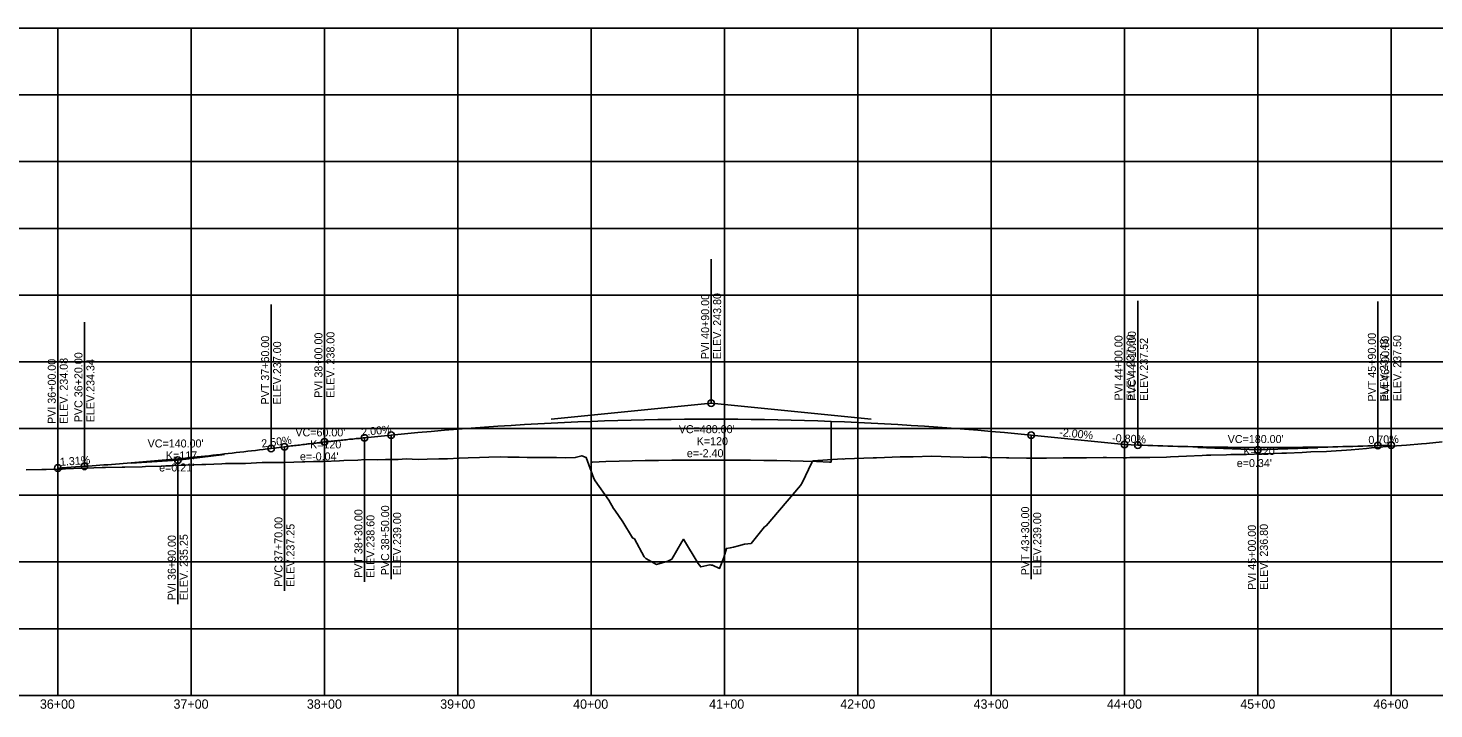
# Model space of a CAD drawing. Extents: x 976639 to 985448, y 1524031 to 1526806.
# Drawn here: x 983504 to 984558, y 1524031 to 1524541 of the extents above; entities that cross this region are included whole.
import ezdxf

# ---------------------------------------------------------------- set-up
doc = ezdxf.new("R2010")
doc.units = 0
for name, color, linetype in [('B_Concrete', 7, 'Continuous'), ('Default', 7, 'Continuous'), ('R_Axis', 7, 'Continuous'), ('R_Axis Annot', 7, 'Continuous'), ('R_Grid', 7, 'Continuous'), ('R_Vert Alg', 7, 'Continuous'), ('R_Vert Alg Annot', 7, 'Continuous'), ('S_WORKING_LINES', 7, 'Continuous')]:
    doc.layers.add(name, color=color, linetype=linetype)

msp = doc.modelspace()

# ---------------------------------------------------------------- linework, layer by layer
at = {"layer": 'B_Concrete'}
for p, q in [((983926.2, 1524246.7), (983926.2, 1524216.2)), ((984106.2, 1524246.7), (984106.2, 1524216.2))]:
    msp.add_line(p, q, dxfattribs=at)
msp.add_lwpolyline([(983926.2, 1524216.2), (983927.3, 1524216.2), (983937.2, 1524216.6), (983947.1, 1524216.9), (983956.9, 1524217.1), (983966.8, 1524217.4), (983976.7, 1524217.5), (983986.6, 1524217.7), (983996.4, 1524217.8), (984006.3, 1524217.8), (984026.1, 1524217.8), (984035.9, 1524217.8), (984045.8, 1524217.7), (984055.7, 1524217.5), (984065.5, 1524217.4), (984075.4, 1524217.1), (984085.3, 1524216.9), (984095.2, 1524216.6), (984105, 1524216.2), (984106.2, 1524216.2)], dxfattribs=at)
at = {"layer": 'Default'}
msp.add_lwpolyline([(983502.5, 1524210.5), (983514.2, 1524210.8), (983517.4, 1524210.8), (983529.4, 1524211), (983532, 1524211.1), (983544.3, 1524211.7), (983547.1, 1524211.8), (983559.4, 1524212.2), (983561.9, 1524212.3), (983574.6, 1524212.4), (983576.6, 1524212.5), (983589.4, 1524212.8), (983591.9, 1524212.9), (983604.3, 1524213.3), (983607.2, 1524213.4), (983619.2, 1524214), (983622.3, 1524214), (983634.3, 1524214.5), (983637.2, 1524214.5), (983649.3, 1524215), (983652.1, 1524215.1), (983664.4, 1524215.1), (983666.9, 1524215.2), (983679.5, 1524215.9), (983681.8, 1524216), (983694.5, 1524216), (983696.8, 1524216), (983709.7, 1524216.4), (983711.4, 1524216.5), (983718.1, 1524216.7), (983724.2, 1524216.8), (983725.3, 1524216.8), (983737.5, 1524217.2), (983740.8, 1524217.4), (983751.2, 1524217.8), (983756.5, 1524218.1), (983766.1, 1524217.9), (983772.1, 1524218.2), (983781.6, 1524218.3), (983787.4, 1524218.6), (983796.5, 1524218.3), (983803.2, 1524218.5), (983811.9, 1524218.6), (983818.5, 1524218.8), (983827.2, 1524219.2), (983834, 1524219.5), (983842.6, 1524219.7), (983849.4, 1524219.9), (983857.9, 1524220.1), (983863.8, 1524219.9), (983872.1, 1524220), (983878.2, 1524219.8), (983886.3, 1524219.8), (983892.6, 1524219.6), (983900.3, 1524219.7), (983906.9, 1524219.5), (983914.3, 1524219.6), (983919.1, 1524221), (983922.5, 1524219.6), (983928.3, 1524204), (983929.2, 1524202.2), (983939.4, 1524187.7), (983943, 1524181.4), (983944, 1524180.2), (983949.9, 1524171.4), (983957.2, 1524159.4), (983958.7, 1524158.7), (983966, 1524145.2), (983966.9, 1524144.3), (983967.3, 1524143.9), (983975.3, 1524139.6), (983983.6, 1524141.9), (983986.7, 1524143.4), (983994.1, 1524156.5), (983995.5, 1524158.4), (984006.4, 1524140.3), (984008.4, 1524137.7), (984015.3, 1524139.3), (984016.2, 1524139.1), (984017.1, 1524139.1), (984022.5, 1524136.5), (984025.7, 1524144.8), (984027.7, 1524151.5), (984030.5, 1524151.9), (984032.9, 1524152.6), (984036.8, 1524153.6), (984041.2, 1524154.8), (984046.1, 1524155.3), (984055.3, 1524166.5), (984056.3, 1524167.7), (984057.4, 1524168.4), (984083.2, 1524198.6), (984084.4, 1524200.8), (984091.8, 1524216), (984092.4, 1524216.7), (984092.7, 1524217.2), (984103.5, 1524218), (984114.8, 1524218.6), (984115.8, 1524218.5), (984116.8, 1524218.6), (984137.6, 1524219.5), (984140.2, 1524219.5), (984158, 1524220.3), (984161.9, 1524220.2), (984167.7, 1524220.1), (984181.4, 1524220.6), (984188.7, 1524220.5), (984195.5, 1524220.1), (984205.1, 1524219.9), (984209.3, 1524219.7), (984218.7, 1524219.9), (984222.7, 1524219.9), (984224, 1524219.8), (984237.7, 1524219.4), (984239.4, 1524219.4), (984252.7, 1524219.3), (984254.7, 1524219.3), (984267.7, 1524219.3), (984280.3, 1524219.4), (984282.7, 1524219.4), (984285.1, 1524219.5), (984297.7, 1524219.4), (984310.3, 1524219.6), (984312.7, 1524219.6), (984312.7, 1524219.6), (984325.3, 1524219.5), (984327.7, 1524219.5), (984330.1, 1524219.6), (984342.7, 1524219.7), (984345.3, 1524219.8), (984357.7, 1524220), (984360.7, 1524220.1), (984372.7, 1524220.6), (984384.5, 1524221.2), (984387.7, 1524221.3), (984390.9, 1524221.4), (984402.7, 1524221.7), (984406, 1524221.8), (984417.7, 1524221.9), (984429.2, 1524222.3), (984432.7, 1524222.5), (984444.3, 1524222.8), (984447.7, 1524223), (984459.5, 1524223.5), (984462.7, 1524223.6), (984465.9, 1524223.8), (984477.7, 1524224.2), (984481.1, 1524224.5), (984492.7, 1524225.2), (984496.2, 1524225.5), (984507.7, 1524226.5), (984511.3, 1524226.8), (984522.7, 1524227.8), (984526.3, 1524228.1), (984537.7, 1524229), (984549, 1524229.8), (984552.7, 1524230.1), (984564.3, 1524231.3)], dxfattribs=at)
at = {"layer": 'R_Axis'}
msp.add_line((982626.2, 1524041.4), (985426.2, 1524041.4), dxfattribs=at)
at = {"layer": 'R_Grid'}
for p, q in [((982626.2, 1524541.4), (985426.2, 1524541.4)), ((982626.2, 1524541.4), (985426.2, 1524541.4)), ((983526.2, 1524041.4), (983526.2, 1524541.4)), ((983626.2, 1524041.4), (983626.2, 1524541.4)), ((983726.2, 1524041.4), (983726.2, 1524541.4)), ((983826.2, 1524041.4), (983826.2, 1524541.4)), ((983926.2, 1524041.4), (983926.2, 1524541.4)), ((984026.2, 1524041.4), (984026.2, 1524541.4)), ((984126.2, 1524041.4), (984126.2, 1524541.4)), ((984226.2, 1524041.4), (984226.2, 1524541.4)), ((984326.2, 1524041.4), (984326.2, 1524541.4)), ((984426.2, 1524041.4), (984426.2, 1524541.4)), ((984526.2, 1524041.4), (984526.2, 1524541.4)), ((982626.2, 1524491.4), (985426.2, 1524491.4)), ((982626.2, 1524441.4), (985426.2, 1524441.4)), ((982626.2, 1524391.4), (985426.2, 1524391.4)), ((982626.2, 1524341.4), (985426.2, 1524341.4)), ((982626.2, 1524291.4), (985426.2, 1524291.4)), ((982626.2, 1524241.4), (985426.2, 1524241.4)), ((982626.2, 1524191.4), (985426.2, 1524191.4)), ((982626.2, 1524141.4), (985426.2, 1524141.4)), ((982626.2, 1524091.4), (985426.2, 1524091.4))]:
    msp.add_line(p, q, dxfattribs=at)
at = {"layer": 'R_Vert Alg'}
for p, q in [((983896.2, 1524248.4), (984016.2, 1524260.4)), ((984016.2, 1524260.4), (984136.2, 1524248.4)), ((983711.2, 1524229.5), (983726.2, 1524231.4)), ((983726.2, 1524231.4), (983741.2, 1524232.9)), ((983756.2, 1524234.4), (983776.2, 1524236.4)), ((984256.2, 1524236.4), (984326.2, 1524229.4)), ((983616.2, 1524217.7), (983651.2, 1524222)), ((983686.2, 1524226.4), (983696.2, 1524227.7)), ((984326.2, 1524229.4), (984336.2, 1524229)), ((984381.2, 1524227.2), (984426.2, 1524225.4)), ((984426.2, 1524225.4), (984471.2, 1524227)), ((984516.2, 1524228.6), (984526.2, 1524228.9)), ((983526.2, 1524211.8), (983546.2, 1524213.1)), ((983581.2, 1524215.4), (983616.2, 1524217.7))]:
    msp.add_line(p, q, dxfattribs=at)
for points in [[(983776.2, 1524236.4), (983786.2, 1524237.4), (983796.2, 1524238.3), (983806.2, 1524239.2), (983816.2, 1524240.1), (983826.2, 1524240.9), (983836.2, 1524241.7), (983846.2, 1524242.4), (983856.2, 1524243.1), (983866.2, 1524243.7), (983876.2, 1524244.3), (983886.2, 1524244.9), (983896.2, 1524245.4), (983906.2, 1524245.9), (983916.2, 1524246.3), (983926.2, 1524246.7), (983936.2, 1524247.1), (983946.2, 1524247.4), (983956.2, 1524247.7), (983966.2, 1524247.9), (983976.2, 1524248.1), (983986.2, 1524248.2), (983996.2, 1524248.3), (984006.2, 1524248.4), (984026.2, 1524248.4), (984036.2, 1524248.3), (984046.2, 1524248.2), (984056.2, 1524248.1), (984066.2, 1524247.9), (984076.2, 1524247.7), (984086.2, 1524247.4), (984096.2, 1524247.1), (984106.2, 1524246.7), (984116.2, 1524246.3), (984126.2, 1524245.9), (984136.2, 1524245.4), (984146.2, 1524244.9), (984156.2, 1524244.3), (984166.2, 1524243.7), (984176.2, 1524243.1), (984186.2, 1524242.4), (984196.2, 1524241.7), (984206.2, 1524240.9), (984216.2, 1524240.1), (984226.2, 1524239.2), (984236.2, 1524238.3), (984246.2, 1524237.4), (984256.2, 1524236.4)], [(983696.2, 1524227.7), (983697.4, 1524227.8), (983698.7, 1524228), (983699.9, 1524228.1), (983701.2, 1524228.3), (983702.4, 1524228.4), (983703.7, 1524228.6), (983704.9, 1524228.7), (983706.2, 1524228.9), (983707.4, 1524229), (983708.7, 1524229.2), (983709.9, 1524229.3), (983711.2, 1524229.5), (983712.4, 1524229.6), (983713.7, 1524229.8), (983714.9, 1524229.9), (983716.2, 1524230.1), (983717.4, 1524230.2), (983718.7, 1524230.4), (983719.9, 1524230.5), (983721.2, 1524230.7), (983722.4, 1524230.8), (983723.7, 1524230.9), (983724.9, 1524231.1), (983727.4, 1524231.4), (983728.7, 1524231.5), (983729.9, 1524231.6), (983731.2, 1524231.8), (983732.4, 1524231.9), (983733.7, 1524232.1), (983734.9, 1524232.2), (983736.2, 1524232.3), (983737.4, 1524232.5), (983738.7, 1524232.6), (983739.9, 1524232.7), (983741.2, 1524232.9), (983742.4, 1524233), (983743.7, 1524233.1), (983744.9, 1524233.3), (983746.2, 1524233.4), (983747.4, 1524233.5), (983748.7, 1524233.7), (983749.9, 1524233.8), (983751.2, 1524233.9), (983752.4, 1524234), (983753.7, 1524234.2), (983754.9, 1524234.3), (983756.2, 1524234.4)], [(983546.2, 1524213.1), (983549.1, 1524213.3), (983552, 1524213.5), (983554.9, 1524213.7), (983557.8, 1524213.9), (983560.8, 1524214.1), (983563.7, 1524214.3), (983566.6, 1524214.5), (983569.5, 1524214.7), (983572.4, 1524215), (983575.3, 1524215.2), (983578.3, 1524215.4), (983581.2, 1524215.6), (983584.1, 1524215.9), (983587, 1524216.1), (983589.9, 1524216.4), (983592.8, 1524216.6), (983595.8, 1524216.9), (983598.7, 1524217.1), (983601.6, 1524217.4), (983604.5, 1524217.6), (983607.4, 1524217.9), (983610.3, 1524218.2), (983613.3, 1524218.4), (983619.1, 1524219), (983622, 1524219.3), (983624.9, 1524219.6), (983627.8, 1524219.9), (983630.8, 1524220.1), (983633.7, 1524220.4), (983636.6, 1524220.7), (983639.5, 1524221), (983642.4, 1524221.4), (983645.3, 1524221.7), (983648.3, 1524222), (983651.2, 1524222.3), (983654.1, 1524222.6), (983657, 1524223), (983659.9, 1524223.3), (983662.8, 1524223.6), (983665.8, 1524224), (983668.7, 1524224.3), (983671.6, 1524224.6), (983674.5, 1524225), (983677.4, 1524225.3), (983680.3, 1524225.7), (983683.3, 1524226.1), (983686.2, 1524226.4)], [(984336.2, 1524229), (984339.9, 1524228.9), (984343.7, 1524228.7), (984347.4, 1524228.6), (984351.2, 1524228.5), (984354.9, 1524228.3), (984358.7, 1524228.2), (984362.4, 1524228.1), (984366.2, 1524228), (984369.9, 1524227.9), (984373.7, 1524227.8), (984377.4, 1524227.7), (984381.2, 1524227.6), (984384.9, 1524227.6), (984388.7, 1524227.5), (984392.4, 1524227.4), (984396.2, 1524227.4), (984399.9, 1524227.3), (984403.7, 1524227.3), (984407.4, 1524227.2), (984411.2, 1524227.2), (984414.9, 1524227.2), (984418.7, 1524227.1), (984422.4, 1524227.1), (984429.9, 1524227.1), (984433.7, 1524227.1), (984437.4, 1524227.1), (984441.2, 1524227.1), (984444.9, 1524227.1), (984448.7, 1524227.1), (984452.4, 1524227.2), (984456.2, 1524227.2), (984459.9, 1524227.3), (984463.7, 1524227.3), (984467.4, 1524227.3), (984471.2, 1524227.4), (984474.9, 1524227.5), (984478.7, 1524227.5), (984482.4, 1524227.6), (984486.2, 1524227.7), (984489.9, 1524227.8), (984493.7, 1524227.9), (984497.4, 1524228), (984501.2, 1524228.1), (984504.9, 1524228.2), (984508.7, 1524228.3), (984512.4, 1524228.4), (984516.2, 1524228.6)]]:
    msp.add_lwpolyline(points, dxfattribs=at)
at = {"layer": 'R_Vert Alg Annot'}
for p, q in [((984016.2, 1524290.4), (984016.2, 1524368.4)), ((983726.2, 1524261.4), (983726.2, 1524339.4)), ((984326.2, 1524259.4), (984326.2, 1524337.4)), ((984336.2, 1524259), (984336.2, 1524337)), ((984516.2, 1524258.6), (984516.2, 1524336.6)), ((984526.2, 1524258.9), (984526.2, 1524336.9)), ((983686.2, 1524256.4), (983686.2, 1524334.4)), ((983526.2, 1524241.8), (983526.2, 1524319.8)), ((983546.2, 1524243.1), (983546.2, 1524321.1)), ((984016.2, 1524260.4), (984016.2, 1524290.4)), ((983686.2, 1524226.4), (983686.2, 1524256.4)), ((983726.2, 1524231.4), (983726.2, 1524261.4)), ((984326.2, 1524229.4), (984326.2, 1524259.4)), ((984336.2, 1524229), (984336.2, 1524259)), ((984516.2, 1524228.6), (984516.2, 1524258.6)), ((984526.2, 1524228.9), (984526.2, 1524258.9)), ((983526.2, 1524211.8), (983526.2, 1524241.8)), ((983546.2, 1524213.1), (983546.2, 1524243.1)), ((983756.2, 1524234.4), (983756.2, 1524204.4)), ((983776.2, 1524236.4), (983776.2, 1524206.4)), ((984256.2, 1524236.4), (984256.2, 1524206.4)), ((983696.2, 1524227.7), (983696.2, 1524197.7)), ((984426.2, 1524225.4), (984426.2, 1524195.4)), ((983616.2, 1524217.7), (983616.2, 1524187.7)), ((983756.2, 1524204.4), (983756.2, 1524126.4)), ((983776.2, 1524206.4), (983776.2, 1524128.4)), ((984256.2, 1524206.4), (984256.2, 1524128.4)), ((983696.2, 1524197.7), (983696.2, 1524119.7)), ((984426.2, 1524195.4), (984426.2, 1524117.4)), ((983616.2, 1524187.7), (983616.2, 1524109.7))]:
    msp.add_line(p, q, dxfattribs=at)
for centre in [(984016.2, 1524260.4), (983726.2, 1524231.4), (983756.2, 1524234.4), (983776.2, 1524236.4), (984256.2, 1524236.4), (984326.2, 1524229.4), (984336.2, 1524229), (984516.2, 1524228.6), (984526.2, 1524228.9), (983686.2, 1524226.4), (983696.2, 1524227.7), (984426.2, 1524225.4), (983526.2, 1524211.8), (983546.2, 1524213.1), (983616.2, 1524217.7)]:
    msp.add_circle(centre, 2.5, dxfattribs=at)
at = {"layer": 'S_WORKING_LINES'}
msp.add_line((983526.2, 1524211), (983526.2, 1524211.8), dxfattribs=at)

# ---------------------------------------------------------------- texts
at = {"layer": 'R_Axis Annot'}
for s, p in [('36+00', (983512.8, 1524031.4)), ('37+00', (983613, 1524031.4)), ('38+00', (983713, 1524031.4)), ('39+00', (983813, 1524031.4)), ('40+00', (983912.7, 1524031.4)), ('41+00', (984014.7, 1524031.4)), ('42+00', (984113, 1524031.4)), ('43+00', (984213, 1524031.4)), ('44+00', (984313, 1524031.4)), ('45+00', (984413, 1524031.4)), ('46+00', (984512.8, 1524031.4))]:
    msp.add_text(s, height=7, dxfattribs=at).set_placement(p)
at = {"layer": 'R_Vert Alg Annot'}
for s, rotation, p in [('PVI 40+90.00', 90, (984014.7, 1524293.4)), ('ELEV. 243.80', 90, (984023.7, 1524293.4)), ('PVT 37+60.00', 90, (983684.7, 1524259.4)), ('ELEV.237.00', 90, (983693.7, 1524259.4)), ('PVI 38+00.00', 90, (983724.7, 1524264.4)), ('ELEV. 238.00', 90, (983733.7, 1524264.4)), ('PVI 44+00.00', 90, (984324.7, 1524262.4)), ('ELEV. 237.60', 90, (984333.7, 1524262.4)), ('PVC 44+10.00', 90, (984334.7, 1524262)), ('ELEV.237.52', 90, (984343.7, 1524262)), ('PVT 45+90.00', 90, (984514.7, 1524261.6)), ('ELEV.237.43', 90, (984523.7, 1524261.6)), ('PVI 46+00.00', 90, (984524.7, 1524261.9)), ('ELEV. 237.50', 90, (984533.7, 1524261.9)), ('PVC 36+20.00', 90, (983544.7, 1524246.1)), ('PVI 36+00.00', 90, (983524.7, 1524244.8)), ('ELEV. 234.08', 90, (983533.7, 1524244.8)), ('ELEV.234.34', 90, (983553.7, 1524246.1)), ('2.00%', 5.7106, (983754.1, 1524235.7)), ('-2.00%', 354.2894, (984277, 1524235.8)), ('2.50%', 7.125, (983679.3, 1524227.1)), ('-0.80%', 357.7094, (984316.8, 1524231.3)), ('0.70%', 1.9951, (984509.2, 1524229.8)), ('1.31%', 3.7339, (983528, 1524213.4)), ('PVT 38+30.00', 90, (983754.7, 1524129.4)), ('PVC 38+50.00', 90, (983774.7, 1524131.4)), ('ELEV.239.00', 90, (983783.7, 1524131.4)), ('PVT 43+30.00', 90, (984254.7, 1524131.4)), ('ELEV.239.00', 90, (984263.7, 1524131.4)), ('PVC 37+70.00', 90, (983694.7, 1524122.7)), ('ELEV.237.25', 90, (983703.7, 1524122.7)), ('ELEV.238.60', 90, (983763.7, 1524129.4)), ('PVI 45+00.00', 90, (984424.7, 1524120.4)), ('ELEV. 236.80', 90, (984433.7, 1524120.4)), ('PVI 36+90.00', 90, (983614.7, 1524112.7)), ('ELEV. 235.25', 90, (983623.7, 1524112.7))]:
    msp.add_text(s, height=6, rotation=rotation, dxfattribs=at).set_placement(p)
for s, p in [("VC=60.00'", (983704.4, 1524235.5)), ("VC=480.00'", (983991.9, 1524237.9)), ("VC=140.00'", (983593.6, 1524227.2)), ('K=120', (983715.4, 1524226.5)), ('K=120', (984005.4, 1524228.9)), ("VC=180.00'", (984403.6, 1524230.5)), ('K=117', (983607.3, 1524218.2)), ("e=-0.04'", (983707.8, 1524217.5)), ("e=-2.40'", (983998, 1524219.9)), ('K=120', (984415.4, 1524221.5)), ("e=0.21'", (983602.2, 1524209.2)), ("e=0.34'", (984410.4, 1524212.5))]:
    msp.add_text(s, height=6, dxfattribs=at).set_placement(p)

doc.saveas('drawing.dxf')
